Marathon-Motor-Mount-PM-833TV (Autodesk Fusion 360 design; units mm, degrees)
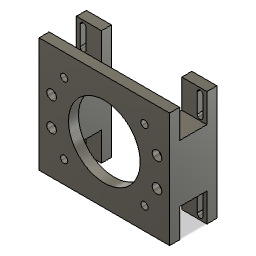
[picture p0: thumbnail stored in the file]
sketch "Motor-Mounting-Plate-Sketch" plane through (0, 0, 0) normal (0, 0, 1) x axis (1, 0, 0)
  line L1 (182, 0) -> (0, 0)
  line L2 (182, 160) -> (182, 0)
  line L3 (0, 160) -> (182, 160)
  line L4 (0, 0) -> (0, 160)
  line L5 (182, 0) -> (0, 160)
  line L6 (182, 160) -> (0, 0)
  line L7 (35, 120) -> (0, 120)
  line L8 (35, 40) -> (35, 120)
  line L9 (0, 40) -> (35, 40)
  line L10 (0, 120) -> (0, 40)
  line L11 (147, 120) -> (182, 120)
  line L12 (147, 40) -> (147, 120)
  line L13 (182, 40) -> (147, 40)
  line L14 (182, 120) -> (182, 40)
  circle C1 centre (91, 80) radius 74.6125
  circle C2 centre (34.963, 129.2633) radius 5
  circle C3 centre (34.963, 30.7367) radius 5
  circle C4 centre (147.037, 30.7367) radius 5
  circle C5 centre (147.037, 129.2633) radius 5
  circle C6 centre (9.45, 20.3) radius 4.15
  circle C7 centre (172.55, 20.3) radius 4.15
  circle C8 centre (9.45, 139.7) radius 4.15
  circle C9 centre (172.55, 139.7) radius 4.15
  circle C10 centre (164.5, 100) radius 4.15
  circle C11 centre (164.5, 60) radius 4.15
  circle C12 centre (17.5, 100) radius 4.15
  circle C13 centre (17.5, 60) radius 4.15
  circle C14 centre (91, 80) radius 50
  circle C15 centre (147.037, 129.2633) radius 7.15
  circle C16 centre (147.037, 30.7367) radius 7.15
  circle C17 centre (34.963, 30.7367) radius 7.15
  circle C18 centre (34.963, 129.2633) radius 7.15
  point P1 (0, 0)
  point P2 (0, 0)
  point P7 (0, 0)
  point P8 (34.963, 129.2633)
  point P9 (34.963, 30.7367)
  point P10 (147.037, 30.7367)
  point P11 (147.037, 129.2633)
  point P16 (0, 120)
  point P20 (182, 120)
  point P3 (182, 0)
  point P5 (0, 160)
  point P6 (91, 80)
  point P12 (9.45, 20.3)
  point P13 (172.55, 20.3)
  point P14 (9.45, 139.7)
  point P15 (172.55, 139.7)
  point P19 (0, 40)
  point P21 (147, 120)
  point P23 (182, 40)
  point P24 (164.5, 100)
  point P25 (164.5, 60)
  point P26 (17.5, 100)
  point P27 (17.5, 60)
  horizontal L1
  vertical L2
  horizontal L3
  vertical L4
  coincident P1 P2
  coincident P1 P7
  coincident C1 P8
  coincident L5 P8
  coincident C1 P9
  coincident L6 P9
  coincident L5 P10
  coincident C1 P10
  coincident C1 P11
  coincident L6 P11
  horizontal L7
  vertical L8
  horizontal L9
  vertical L10
  coincident L4 P16
  horizontal L11
  vertical L12
  horizontal L13
  vertical L14
  coincident L2 P20
  concentric C1 C14
  concentric C5 C15
  concentric C4 C16
  concentric C3 C17
  concentric C2 C18
  dimension "d1" distance P2 P3 = 182
  dimension "d2" distance P2 P5 = 160
  dimension "d3" diameter C1 = 149.225
  dimension "d4" distance L4 P6 = 91 (= "d1 / 2")
  dimension "d5" distance P1 P6 = 80 (= "d2 / 2")
  dimension "d6" diameter C2 = 10
  dimension "d7" diameter C3 = 10
  dimension "d8" diameter C4 = 10
  dimension "d9" diameter C5 = 10
  dimension "d10" diameter C6 = 8.3
  dimension "d11" diameter C7 = 8.3
  dimension "d12" distance P12 P13 = 163.1
  dimension "d13" distance L2 P13 = 9.45 (= "( d1 - d12 ) / 2")
  dimension "d14" diameter C8 = 8.3
  dimension "d15" diameter C9 = 8.3
  dimension "d16" distance P14 P15 = 163.1
  dimension "d17" distance L2 P15 = 9.45 (= "d13")
  dimension "d18" distance P13 P15 = 119.4
  dimension "d19" distance L1 P13 = 20.3 (= "( d2 - d18 ) / 2")
  dimension "d20" distance P12 P14 = 119.4
  dimension "d21" distance L1 P12 = 20.3 (= "d19")
  dimension "d22" distance P16 P19 = 80
  dimension "d23" distance L1 L9 = 40 (= "( d2 - d22 ) / 2")
  dimension "d24" distance L4 L8 = 35
  dimension "d25" distance P20 P21 = 35
  dimension "d26" distance P20 P23 = 80
  dimension "d27" distance L1 L13 = 40 (= "d23")
  dimension "d28" diameter C10 = 8.3
  dimension "d30" diameter C11 = 8.3
  dimension "d31" distance L11 P24 = 20
  dimension "d34" distance L12 P24 = 17.5
  dimension "d36" distance L12 P25 = 17.5
  dimension "d37" diameter C12 = 8.3
  dimension "d39" diameter C13 = 8.3
  dimension "d40" distance L10 P26 = 17.5 (= "( 35 / 2 ) * 1 mm")
  dimension "d42" distance L4 P27 = 17.5
  dimension "d43" distance L9 P27 = 20
  dimension "d56" diameter C14 = 100
  dimension "d71" diameter C15 = 14.3
  dimension "d72" diameter C16 = 14.3
  dimension "d73" diameter C17 = 14.3
  dimension "d74" diameter C18 = 14.3
  dimension "d75" distance L13 P25 = 20
  dimension "d76" distance L7 P26 = 20
extrude "Extrude1" new body sketch "Motor-Mounting-Plate-Sketch" profile of L1 L2 L3 L4 C2 C3 C4 C5 L7 L8 L9 L10 L11 L12 L13 L14 C10 C11 C12 C13 C14 along normal blind 14
sketch "Motor-Mounting-Plate-Counterbore" plane through (0, 0, 14) normal (0, 0, 1) x axis (1, 0, 0)
  line L1 (0, 0) -> (0, 160)
  line L2 (182, 0) -> (0, 0)
  line L3 (182, 160) -> (182, 0)
  line L4 (0, 160) -> (182, 160)
  circle C1 centre (147.037, 30.7367) radius 5
  circle C2 centre (34.963, 30.7367) radius 5
  circle C3 centre (34.963, 129.2633) radius 5
  circle C4 centre (17.5, 60) radius 4.15
  circle C5 centre (17.5, 100) radius 4.15
  circle C6 centre (164.5, 60) radius 4.15
  circle C7 centre (164.5, 100) radius 4.15
  circle C8 centre (147.037, 129.2633) radius 5
  circle C9 centre (17.5, 100) radius 6.75
  circle C10 centre (17.5, 60) radius 6.75
  circle C11 centre (164.5, 100) radius 6.75
  circle C12 centre (164.5, 60) radius 6.75
  circle C13 centre (91, 80) radius 50
  concentric C5 C9
  concentric C4 C10
  concentric C7 C11
  concentric C6 C12
  dimension "d48" diameter C9 = 13.5
  dimension "d50" diameter C10 = 13.5
  dimension "d51" diameter C11 = 13.5
  dimension "d53" diameter C12 = 13.5
extrude "Extrude2" cut sketch "Motor-Mounting-Plate-Counterbore" profile of C4 C5 C6 C7 C9 C10 C11 C12 against normal blind 9
extrude "Extrude3" add sketch "Motor-Mounting-Plate-Sketch" profile of L2 L4 L7 L8 L9 L10 L11 L12 L13 L14 C10 C11 C12 C13 against normal blind 38
sketch "Base-Feet" plane through (0, 0, -38) normal (0, 0, -1) x axis (-1, 0, 0)
  line L1 (-182, 40) -> (-182, 120)
  line L2 (-147, 40) -> (-182, 40)
  line L3 (-147, 120) -> (-147, 40)
  line L4 (-182, 120) -> (-147, 120)
  line L5 (-147, 160) -> (-182, 160)
  line L6 (-147, 0) -> (-147, 160)
  line L7 (-182, 0) -> (-147, 0)
  line L8 (-182, 160) -> (-182, 0)
  line L9 (-35, 0) -> (0, 0)
  line L10 (-35, 160) -> (-35, 0)
  line L11 (0, 160) -> (-35, 160)
  line L12 (0, 0) -> (0, 160)
  line L13 (-182, 0) -> (0, 0)
  line L14 (0, 160) -> (-182, 160)
  line L15 (-182, 160) -> (-182, 0)
  line L16 (-182, 40) -> (-147, 40)
  line L17 (-176.7, 6.5) -> (-176.7, 33.5)
  line L18 (-168.4, 33.5) -> (-168.4, 6.5)
  line L19 (-5.3, 33.5) -> (-5.3, 6.5)
  line L20 (-13.6, 6.5) -> (-13.6, 33.5)
  line L21 (-168.4, 152.9) -> (-168.4, 125.9)
  line L22 (-176.7, 125.9) -> (-176.7, 152.9)
  line L23 (-5.3, 152.9) -> (-5.3, 125.9)
  line L24 (-13.6, 125.9) -> (-13.6, 152.9)
  circle C1 centre (-164.5, 60) radius 4.15
  circle C2 centre (-164.5, 100) radius 4.15
  circle C3 centre (-172.55, 139.7) radius 4.15
  circle C4 centre (-172.55, 20.3) radius 4.15
  circle C5 centre (-9.45, 20.3) radius 4.15
  circle C6 centre (-9.45, 139.7) radius 4.15
  circle C7 centre (-172.55, 33.5) radius 4.15
  circle C8 centre (-172.55, 6.5) radius 4.15
  circle C9 centre (-147.037, 129.2633) radius 7.15
  circle C10 centre (-147.037, 30.7367) radius 7.15
  circle C11 centre (-34.963, 30.7367) radius 7.15
  circle C12 centre (-34.963, 129.2633) radius 7.15
  circle C13 centre (-34.963, 129.2633) radius 8.15
  circle C14 centre (-147.037, 129.2633) radius 8.15
  circle C15 centre (-147.037, 30.7367) radius 8.15
  circle C16 centre (-172.55, 33.5) radius 6.5
  circle C17 centre (-9.45, 6.5) radius 4.15
  circle C18 centre (-9.45, 33.5) radius 4.15
  circle C19 centre (-172.55, 125.9) radius 4.15
  circle C20 centre (-172.55, 152.9) radius 4.15
  circle C21 centre (-9.45, 125.9) radius 4.15
  circle C22 centre (-9.45, 152.9) radius 4.15
  point P1 (0, 0)
  point P12 (0, 0)
  point P39 (-176.7, 33.5)
  point P41 (-168.4, 6.5)
  point P42 (-168.4, 33.5)
  point P59 (-13.6, 125.9)
  point P13 (-35, 0)
  point P25 (-172.55, 33.5)
  point P26 (-172.55, 6.5)
  point P20 (-172.55, 139.7)
  point P43 (-172.55, 20.3)
  horizontal L5
  vertical L6
  horizontal L7
  vertical L8
  horizontal L9
  vertical L10
  horizontal L11
  vertical L12
  coincident P1 P12
  collinear L7 L13
  collinear L5 L14
  collinear L8 L15
  concentric C7 C16
  coincident C7 P39
  tangent C7 L17
  parallel L15 L17
  coincident C8 P41
  coincident C7 P42
  tangent C7 L18
  parallel L17 L18
  coincident P59 C21
  collinear L11 L14
  dimension "d65" distance P12 P13 = 35
  dimension "d66" distance L6 L8 = 35
  dimension "d69" diameter C7 = 8.3
  dimension "d70" diameter C8 = 8.3
  dimension "d77" = 1
  dimension "d78" = 1
  dimension "d79" = 1
  dimension "d80" distance L8 P25 = 9.45
  dimension "d81" diameter C16 = 13
  dimension "d82" distance P25 L16 = 6.5
  dimension "d83" distance L7 P26 = 6.5
  dimension "d84" distance L8 P26 = 9.45
  dimension "d85" distance P20 P43 = 119.4
  dimension "d88" R-Pattern1-uDistance = 163.1
  dimension "d89" R-Pattern1-vDistance = 119.4
extrude "Extrude4" add sketch "Base-Feet" profile of C1 C2 L1 L2 L3 L4 L5 L6 L7 L8 L9 L10 L11 L12 L13 L14 C7 C8 L15 C9 C10 C11 C12 C13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 along normal blind 14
